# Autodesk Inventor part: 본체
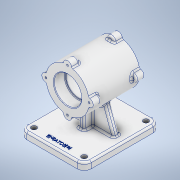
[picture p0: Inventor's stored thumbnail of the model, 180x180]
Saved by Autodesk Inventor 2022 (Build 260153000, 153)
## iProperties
Created: 2023-05
Part Number: 본체
Material: 알루미늄 6061
Document SubType Name: Modeling
Designer: Admin
Mass: 1215.39 g
Surface Area: 796.917 cm^2
Volume: 450.145 cm^3
Density: 2.7 g/cm^3
Appearance: 알루미늄 - 평지
Author: Admin
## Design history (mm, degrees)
sketch "스케치1"
  geometry: L1 (55, 70)-(-55, 70); L2 (-55, 70)-(-55, -60); L3 (-55, -60)-(55, -60); L4 (55, -60)-(55, 70); L5 (0, -86)-(0, 96) reference; L6 (77, 0)-(-77, 0) reference
  constraints: 8 end point, 2 parallel, 1 horizontal, 1 perpendicular, 1 other
  dimensions: "d63" = 130 distance of L3.end L1.start; "d64" = 110 distance of L2.end L3.end; "d65" = 70 distance between parallel lines of L1 L6
extrude "돌출1" new body sketch "스케치1" distance "d2" = 12; taper "d3" = 0 deg
sketch "스케치11"
  geometry: L1 (0, -2.4)-(0, 14.4) reference; L2 (-77, 0)-(77, 0) reference; C1 r 37 at (0, 82); 1 further point
  constraints: 1 centre point, 1 point on line
  dimensions: "d66" = 74 diameter of C1; "d67" = 82 distance from line of L2 C1.centre
extrude "돌출7" join sketch "스케치11" stored distance "d68" = 87; taper "d69" = 0 deg
sketch "스케치12"
  geometry: L1 (5, 20)-(-5, 20); L2 (-5, 20)-(-5, -20); L3 (-5, -20)-(5, -20); L4 (5, -20)-(5, 20); L5 (-77, 0)-(77, 0) reference; L6 (0, -86)-(0, 96) reference; 1 further point
  constraints: 8 end point, 2 parallel, 1 horizontal, 1 perpendicular, 2 other
  dimensions: "d70" = 40 distance of L3.end L1.start; "d71" = 10 distance of L2.end L3.end
extrude "돌출8" join sketch "스케치12" stored distance "d72" = 10; taper "d73" = 0 deg
sketch "스케치13"
  geometry: L1 (55, 12)-(-55, 12) reference; L2 (-41, 12)-(-20.247, 69.019); L3 (-55, 0)-(-55, 12) reference; 1 further point
  constraints: 2 end point, 1 point on line
  dimensions: "d74" = 14 distance from line of L3 L2.start; "d75" = 110 deg angle of L1 L2
feature "리브2" sketch "스케치13" dims "d76" = 1, "d77" = 10, "d78" = 0, "d79" = 0, "d80" = 1, "d81" = 1
sketch "스케치14"
  geometry: L1 (0, -105.8)-(0, 60.8) reference; C1 r 37 at (0, 0) reference; C2 r 7 at (0, 37); 2 further points
  constraints: 1 centre point, 1 point on line, 1 vertical alignment, 1 other
  dimensions: "d82" = 14 diameter of C2
extrude "돌출9" join sketch "스케치14" distance "d83" = 14; taper "d84" = 0 deg
sketch "스케치15"
  geometry: A1 r 7 centre (0, 119) between (6.969, 118.338) and (-6.969, 118.338) reference; 2 further points
  constraints: 1 coincident
hole "구멍2" sketch "스케치15" at (0, 119) diameter "d85" = 3.242; stored, may be unused: countersink angle "d89" = 90 deg, drill point angle "d91" = 118 deg; dims "d86" = 8, "d87" = 4, "d88" = 2, "d90" = 10
fillet "모깎기5" dims "d95" = 12
sketch "스케치16"
  geometry: L1 (82, 66.7)-(82, -66.473); L2 (0, -48)-(0, 58) reference; L3 (89, 43.5)-(75, 43.5) reference; L4 (82, 43.5)-(105.5, 43.5); L5 (105.5, 43.5)-(105.5, 24.5); L6 (105.5, 24.5)-(82, 24.5); L7 (82, 24.5)-(82, 43.5); L8 (82, 24.5)-(103, 24.5); L9 (103, 24.5)-(103, -24.5); L10 (103, -24.5)-(82, -24.5); L11 (82, -24.5)-(82, 24.5); L12 (88.969, -43.5)-(118.338, -43.5) reference; L13 (82, -24.5)-(105.5, -24.5); L14 (105.5, -24.5)-(105.5, -43.5); L15 (105.5, -43.5)-(82, -43.5); L16 (82, -43.5)-(82, -24.5); 7 further points
  constraints: 26 end point, 6 parallel, 3 horizontal, 3 perpendicular, 1 midpoint, 1 point on line, 1 vertical
  dimensions: "d96" = 82 distance between parallel lines of L2 L1; "d97" = 47 diameter of L5 L1; "d98" = 42 diameter of L9 L1; "d99" = 47 diameter of L14 L1; "d100" = 19 distance of L4.end L5.end; "d101" = 19 distance of L13.end L14.end
revolve "회전2" sketch "스케치16" stored, may be unused: angle "d102" = 90 deg
sketch "스케치17"
  geometry: L1 (0, 86)-(0, -96) reference; 2 further points
  constraints: 1 point on line, 1 other
  dimensions: "d103" = 58 distance of point (0, 0) point (0, -58)
feature "엠보싱2" sketch "스케치17" dims "d104" = 0.5, "d105" = 0
fillet "모깎기6" dims "d106" = 3
fillet "모깎기7" dims "d107" = 3
fillet "모깎기8" dims "d108" = 3
chamfer "모따기2" distance "d109" = 1; stored, may be unused: second distance "d110" = 2, angle "d111" = 45 deg
fillet "모깎기9" dims "d112" = 1
sketch "스케치18"
  geometry: C1 r 4.5 at (-43, -58); A1 r 12 centre (-43, -58) between (-55, -58) and (-43, -70) reference; 1 further point
  constraints: 1 centre point, 1 coincident
  dimensions: "d113" = 9 diameter of C1
extrude "돌출10" cut sketch "스케치18" extent not by distance; stored distance "d114" = 0; taper "d115" = 0 deg
sketch "스케치19"
  geometry: C1 r 4.5 at (-43, 48); A1 r 12 centre (-43, 48) between (-43, 60) and (-55, 48) reference; 1 further point
  constraints: 1 centre point, 1 coincident
  dimensions: "d116" = 9 diameter of C1
extrude "돌출11" cut sketch "스케치19" extent not by distance; stored distance "d117" = 0; taper "d118" = 0 deg
node "솔리드1"
mirror "미러8"
pattern_circular "원형 패턴3" dims angle "d93" = 360 deg
mirror "미러9"
mirror "미러10"
mirror "미러11"
feature "A9D066F2-1C7D-4E18-AEED-F7BC21143FA4" dims "d85" = 3.242, "d86" = 8, "d87" = 4, "d88" = 2, "d89" = 90 deg, "d90" = 10, "d91" = 118 deg
